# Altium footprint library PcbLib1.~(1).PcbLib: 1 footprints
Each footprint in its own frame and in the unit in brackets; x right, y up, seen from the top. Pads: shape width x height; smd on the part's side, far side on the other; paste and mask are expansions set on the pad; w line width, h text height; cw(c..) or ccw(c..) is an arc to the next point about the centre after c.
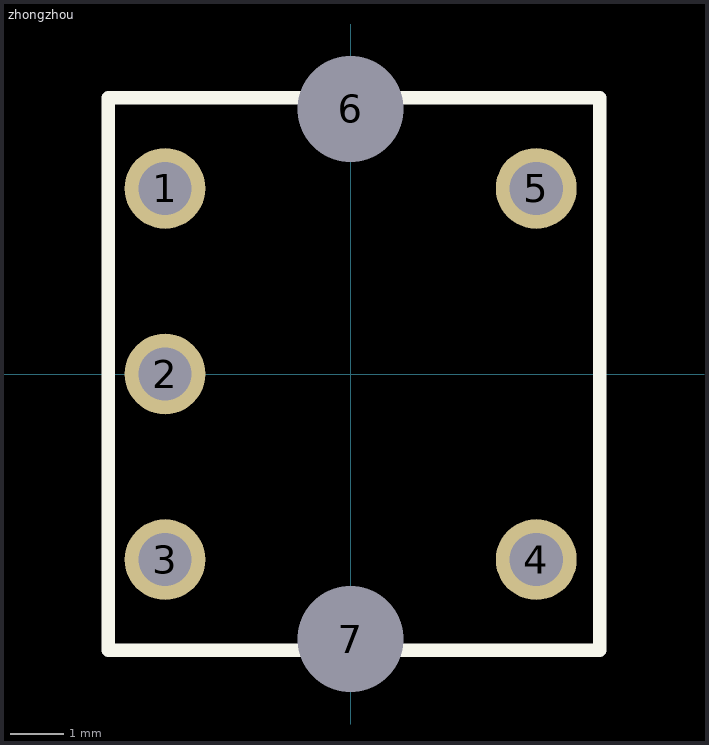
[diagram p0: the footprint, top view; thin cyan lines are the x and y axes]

## zhongzhou [mm]
pads (7):
  round 1.524 hole 1: 1(-3.5,3.5) 2(-3.5,0) 3(-3.5,-3.5) 4(3.5,-3.5) 5(3.5,3.5)
  round 1.524 hole 2: 6(0,5) 7(0,-5)
Top Overlay:
  lines w0.254: -4.572,-5.207 -1.143,-5.207 4.699,-5.207 4.699,5.207 1.143,5.207 -4.572,5.207 -4.572,-5.207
